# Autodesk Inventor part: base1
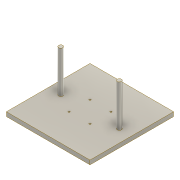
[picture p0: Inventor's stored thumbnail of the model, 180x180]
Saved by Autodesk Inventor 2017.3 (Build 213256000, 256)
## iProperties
Part Number: base1
Material: チタン
Document SubType Name: Modeling
Designer: kyushu-hep
Density: 4.51 g/cm^3
Appearance: チタン
Author: kyushu-hep
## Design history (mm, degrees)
sketch "スケッチ3"
  geometry: L1 (-100, 100)-(100, 100); L2 (100, 100)-(100, -100); L3 (100, -100)-(-100, -100); L4 (-100, -100)-(-100, 100); 1 further point
  constraints: 8 end point, 2 parallel, 1 horizontal, 1 perpendicular
  dimensions: "d19" = 100 distance from line of L1 point (0, 0); "d20" = 200 distance of L3.end L1.start; "d21" = 200 distance of L1.start L1.end; "d22" = 100 distance from line of L4 point (0, 0)
extrude "押し出し3" new body sketch "スケッチ3" distance "d23" = 10; taper "d24" = 0 deg
sketch "スケッチ4"
  geometry: C1 r 5 at (-70, 0); C2 r 5 at (70, 0); 1 further point
  constraints: 2 centre point
  dimensions: "d25" = 10 diameter of C1; "d26" = 10 diameter of C2; "d27" = 70 distance of point (0, 0) C1.centre; "d28" = 70 distance of C2.centre point (0, 0)
extrude "押し出し4" join sketch "スケッチ4" distance "d29" = 100; taper "d30" = 0 deg
sketch "スケッチ6"
  geometry: L1 (52, -52)-(-52, -52); L2 (-52, -52)-(-52, 52); L3 (-52, 52)-(52, 52); L4 (52, 52)-(52, -52); L5 (52, -52)-(-52, 52); L6 (-52, -52)-(52, 52); C1 r 2 at (-25, 25); C2 r 2 at (25, 25); C3 r 2 at (-25, -25); C4 r 2 at (25, -25); 1 further point
  constraints: 12 end point, 4 centre point, 2 horizontal, 2 midpoint, 2 parallel, 1 perpendicular, 1 vertical, 6 other
  dimensions: "d38" = 4 diameter of C1; "d40" = 25 horizontal distance of point (0, 0) C1.centre; "d43" = 50 distance of C1.centre C2.centre; "d46" = 50 distance of C1.centre C3.centre; "d51" = 25 horizontal distance of point (0, 0) C2.centre
extrude "押し出し6" cut sketch "スケッチ6" distance "d49" = 10; taper "d50" = 0 deg
node "ソリッド2"
